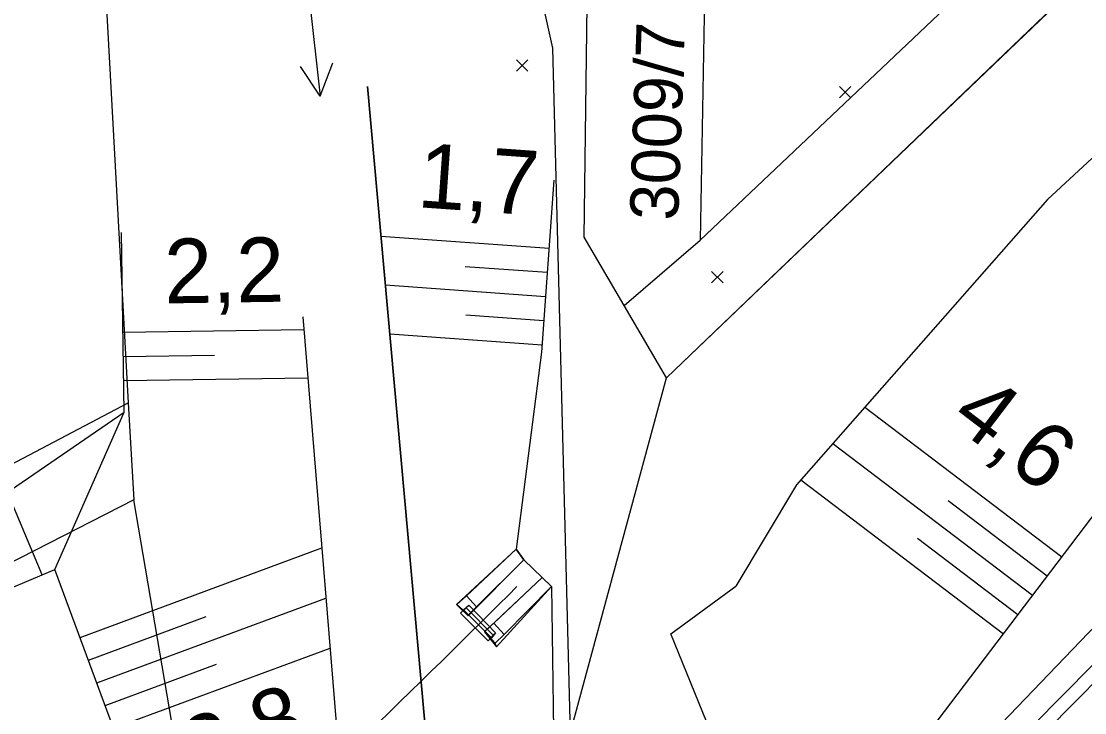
# Model space of a CAD drawing. Extents: x -800194 to -799078, y -1007177 to -1006597.
# Drawn here: x -799442.55 to -799409.59, y -1006874.74 to -1006853.31 of the extents above; entities that cross this region are included whole.
import ezdxf

# ---------------------------------------------------------------- set-up
doc = ezdxf.new("R2010")
doc.units = 0
for name, color, linetype in [('Vrstva 12', 7, 'Continuous'), ('Vrstva 23', 7, 'Continuous'), ('Vrstva 4', 7, 'Continuous'), ('Vrstva 47', 7, 'Continuous'), ('Vrstva 48', 7, 'Continuous'), ('Vrstva 49', 7, 'Continuous'), ('Vrstva 50', 7, 'Continuous'), ('Vrstva 53', 7, 'Continuous'), ('Vrstva 55', 7, 'Continuous'), ('Vrstva 57', 7, 'Continuous'), ('Vrstva 58', 7, 'Continuous')]:
    doc.layers.add(name, color=color, linetype=linetype)

msp = doc.modelspace()

# ---------------------------------------------------------------- linework, layer by layer
at = {"layer": 'Vrstva 12'}
for p, q in [((-799428.684, -1006871.709), (-799429.052, -1006871.381)), ((-799427.855, -1006872.588), (-799428.189, -1006872.226))]:
    msp.add_line(p, q, dxfattribs=at)
for points in [[(-799427.212, -1006869.673), (-799429.053, -1006871.381), (-799428.701, -1006871.731), (-799426.968, -1006870.003)], [(-799427.212, -1006869.673), (-799428.749, -1006871.113), (-799428.434, -1006871.455), (-799426.968, -1006870.003), (-799427.212, -1006869.673)], [(-799426.4, -1006870.552), (-799428.191, -1006872.229), (-799427.819, -1006872.693), (-799426.115, -1006870.824)], [(-799426.4, -1006870.552), (-799426.115, -1006870.824), (-799427.583, -1006872.312), (-799427.902, -1006871.962), (-799426.4, -1006870.552)], [(-799428.749, -1006871.113), (-799429.052, -1006871.381), (-799429.053, -1006871.381)], [(-799428.434, -1006871.455), (-799428.684, -1006871.709), (-799428.701, -1006871.731)], [(-799427.902, -1006871.962), (-799428.189, -1006872.226), (-799428.191, -1006872.229)], [(-799427.819, -1006872.693), (-799427.855, -1006872.588), (-799427.583, -1006872.312)]]:
    msp.add_lwpolyline(points, dxfattribs=at)
at = {"layer": 'Vrstva 23'}
for p, q in [((-799428.839, -1006871.551), (-799427.97, -1006872.42)), ((-799427.924, -1006872.333), (-799428.753, -1006871.491)), ((-799428.675, -1006871.409), (-799427.852, -1006872.259)), ((-799428.071, -1006872.51), (-799428.937, -1006871.65))]:
    msp.add_line(p, q, dxfattribs=at)
for points in [[(-799428.937, -1006871.65), (-799428.839, -1006871.551), (-799428.675, -1006871.409), (-799428.753, -1006871.491), (-799428.937, -1006871.65)], [(-799427.924, -1006872.333), (-799427.852, -1006872.259), (-799427.97, -1006872.42), (-799428.071, -1006872.51), (-799427.924, -1006872.333)]]:
    msp.add_lwpolyline(points, dxfattribs=at)
at = {"layer": 'Vrstva 4'}
for points in [[(-799415.349, -1006878.386), (-799401.641, -1006864.104), (-799387.486, -1006849.959), (-799372.535, -1006834.618), (-799359.471, -1006821.017), (-799348.425, -1006810.321), (-799332.246, -1006792.656), (-799316.193, -1006777.023)], [(-799414.896, -1006878.87), (-799401.02, -1006864.85), (-799386.827, -1006850.567), (-799372.152, -1006835.069), (-799358.827, -1006821.464), (-799347.624, -1006811), (-799330.977, -1006793.164), (-799315.559, -1006777.544)], [(-799510.394, -1006958.536), (-799498.027, -1006951.328), (-799477.988, -1006937.435), (-799460.33, -1006923.117), (-799451.862, -1006915.581), (-799443.604, -1006907.9), (-799435.444, -1006900.067), (-799428.64, -1006893.299), (-799422.817, -1006887.511), (-799415.998, -1006880.595), (-799408.158, -1006872.652), (-799401.02, -1006864.85)]]:
    msp.add_lwpolyline(points, dxfattribs=at)
at = {"layer": 'Vrstva 47'}
msp.add_ellipse((-799432.733, -1006875.845), major_axis=(8.482, 8.158), ratio=0.02521, start_param=4.117511, end_param=5.400082, dxfattribs=at)
at = {"layer": 'Vrstva 48'}
for p, q in [((-799426.189, -1006860.351), (-799431.398, -1006859.979)), ((-799426.243, -1006861.099), (-799428.786, -1006860.917)), ((-799426.296, -1006861.847), (-799431.261, -1006861.492)), ((-799426.349, -1006862.595), (-799428.771, -1006862.422)), ((-799439.39, -1006862.948), (-799433.792, -1006862.864)), ((-799426.403, -1006863.343), (-799431.124, -1006863.006)), ((-799439.379, -1006863.698), (-799436.554, -1006863.656)), ((-799439.368, -1006864.447), (-799433.668, -1006864.363)), ((-799410.295, -1006869.914), (-799416.403, -1006865.276)), ((-799411.202, -1006871.109), (-799417.396, -1006866.406)), ((-799412.109, -1006872.303), (-799418.389, -1006867.535)), ((-799441.897, -1006870.468), (-799442.971, -1006867.903)), ((-799410.749, -1006870.511), (-799413.824, -1006868.176)), ((-799440.726, -1006872.404), (-799433.232, -1006869.633)), ((-799411.656, -1006871.706), (-799414.774, -1006869.338)), ((-799440.206, -1006873.811), (-799433.104, -1006871.185)), ((-799440.466, -1006873.108), (-799436.817, -1006871.758)), ((-799439.685, -1006875.218), (-799432.976, -1006872.737)), ((-799439.946, -1006874.515), (-799436.493, -1006873.238))]:
    msp.add_line(p, q, dxfattribs=at)
at = {"layer": 'Vrstva 49'}
for p, q in [((-799427.202, -1006854.504), (-799426.848, -1006854.858)), ((-799427.202, -1006854.858), (-799426.848, -1006854.504)), ((-799417.188, -1006855.332), (-799416.834, -1006855.686)), ((-799417.188, -1006855.686), (-799416.834, -1006855.332)), ((-799421.151, -1006861.062), (-799420.797, -1006861.416)), ((-799421.151, -1006861.416), (-799420.797, -1006861.062))]:
    msp.add_line(p, q, dxfattribs=at)
for points in [[(-799327.095, -1006776.084), (-799339.676, -1006790.63), (-799358.716, -1006807.195), (-799375.729, -1006824.95), (-799393.254, -1006842.64), (-799410.738, -1006858.834), (-799418.516, -1006867.679), (-799420.397, -1006870.813)], [(-799416.02, -1006877.454), (-799404.211, -1006861.901), (-799389.752, -1006848.65), (-799373.943, -1006833.474), (-799360.851, -1006819.663), (-799350.223, -1006808.887), (-799332.885, -1006792.133), (-799317.349, -1006776.174)], [(-799410.227, -1006925.149), (-799412.491, -1006911.033), (-799419.106, -1006898.668), (-799423.582, -1006889.778), (-799429.735, -1006878.378), (-799431.818, -1006855.328)], [(-799426.038, -1006858.234), (-799426.419, -1006863.568), (-799427.212, -1006869.673), (-799426.968, -1006870.003), (-799426.4, -1006870.552), (-799426.115, -1006870.824), (-799426.018, -1006877.519), (-799424.103, -1006883.903), (-799422.705, -1006885.358), (-799423.751, -1006886.402), (-799420.096, -1006889.979), (-799419.086, -1006888.964), (-799412.022, -1006900.113), (-799405.487, -1006924.286)], [(-799427.694, -1006890.471), (-799427.892, -1006890.566), (-799432.944, -1006889.197), (-799436.923, -1006881.42), (-799437.363, -1006881.152), (-799437.876, -1006880.464), (-799438.146, -1006880.193), (-799438.528, -1006878.348), (-799441.503, -1006870.303), (-799439.353, -1006865.427), (-799439.436, -1006859.851)], [(-799433.824, -1006862.471), (-799432.369, -1006880.085), (-799427.694, -1006890.471)], [(-799461.444, -1006891.51), (-799455.403, -1006884.501), (-799445.66, -1006878.142), (-799444.968, -1006869.269), (-799439.353, -1006865.427)], [(-799461.444, -1006891.51), (-799453.63, -1006885.576), (-799442.951, -1006879.899), (-799443.72, -1006871.232), (-799441.503, -1006870.303)], [(-799418.695, -1006881.438), (-799422.419, -1006872.299), (-799420.397, -1006870.813)]]:
    msp.add_lwpolyline(points, dxfattribs=at)
at = {"layer": 'Vrstva 50'}
for points in [[(-799431.818, -1006855.328), (-799429.735, -1006878.378), (-799423.582, -1006889.778), (-799419.106, -1006898.668), (-799412.491, -1006911.033), (-799410.227, -1006925.149)], [(-799433.824, -1006862.471), (-799432.369, -1006880.085), (-799427.694, -1006890.471), (-799424.101, -1006893.992), (-799424.223, -1006894.144), (-799421.688, -1006901.262), (-799414.969, -1006911.36), (-799413.387, -1006925.296)]]:
    msp.add_lwpolyline(points, dxfattribs=at)
at = {"layer": 'Vrstva 53'}
msp.add_lwpolyline([(-799559.64, -1006968.48), (-799519.68, -1006952.01), (-799500.87, -1006940.41), (-799496.64, -1006937.8), (-799494.85, -1006936.7), (-799484.519, -1006930.319), (-799457.99, -1006908.8), (-799435, -1006885.17), (-799430.26, -1006880.27), (-799425.53, -1006875.38), (-799422.55, -1006864.36), (-799390.88, -1006834), (-799358.35, -1006806.65), (-799352.29, -1006801.56), (-799330.91, -1006783.58), (-799314.235, -1006766.649)], dxfattribs=at)
at = {"layer": 'Vrstva 55'}
for p, q in [((-799390.88, -1006834), (-799422.55, -1006864.36)), ((-799421.3, -1006848.64), (-799421.51, -1006860.09)), ((-799423.86, -1006862.12), (-799421.51, -1006860.09)), ((-799422.55, -1006864.36), (-799423.86, -1006862.12)), ((-799425.53, -1006875.38), (-799422.55, -1006864.36)), ((-799439.23, -1006865.13), (-799439.06, -1006868.14))]:
    msp.add_line(p, q, dxfattribs=at)
for points in [[(-799435.887, -1006766.649), (-799434.45, -1006772.74), (-799433.92, -1006782.05), (-799434.12, -1006788.57), (-799439.66, -1006821.53), (-799440.71, -1006838.23), (-799439.23, -1006865.13)], [(-799422.547, -1006766.649), (-799420.88, -1006776.85), (-799422, -1006788.79), (-799422.77, -1006803.25), (-799426.4, -1006820.84), (-799428.26, -1006838.83), (-799427.88, -1006846.03), (-799426.08, -1006854.14), (-799425.53, -1006875.38)], [(-799421.51, -1006860.09), (-799407.9, -1006847.2), (-799393.66, -1006833.58), (-799374.69, -1006803.75)], [(-799423.86, -1006862.12), (-799425.1, -1006860), (-799425, -1006852)], [(-799498.58, -1006896.8), (-799468.62, -1006880.61), (-799439.23, -1006865.13)], [(-799439.06, -1006868.14), (-799466.75, -1006882.3), (-799482.8, -1006890.48), (-799499.57, -1006898.99), (-799506.49, -1006901.85)], [(-799435, -1006885.17), (-799437.37, -1006878.01), (-799439.06, -1006868.14)]]:
    msp.add_lwpolyline(points, dxfattribs=at)
at = {"layer": 'Vrstva 58'}
for p, q in [((-799433.933, -1006849.66), (-799433.288, -1006855.625)), ((-799433.288, -1006855.625), (-799433.893, -1006854.707)), ((-799433.288, -1006855.625), (-799432.895, -1006854.6))]:
    msp.add_line(p, q, dxfattribs=at)

# ---------------------------------------------------------------- texts
at = {"layer": 'Vrstva 48'}
for s, rotation, p in [('1,7', 355.9144, (-799430.298, -1006859.067)), ('2,2', 0.8528, (-799438.104, -1006862.054)), ('4,6', 322.7915, (-799413.815, -1006865.73)), ('2,8', 20.2941, (-799437.062, -1006876.949))]:
    msp.add_text(s, height=2, rotation=rotation, dxfattribs=at).set_placement(p)
at = {"layer": 'Vrstva 57'}
msp.add_text('3009/7', height=1.5, rotation=88, dxfattribs=at).set_placement((-799422.19, -1006859.499))

doc.saveas('drawing.dxf')
